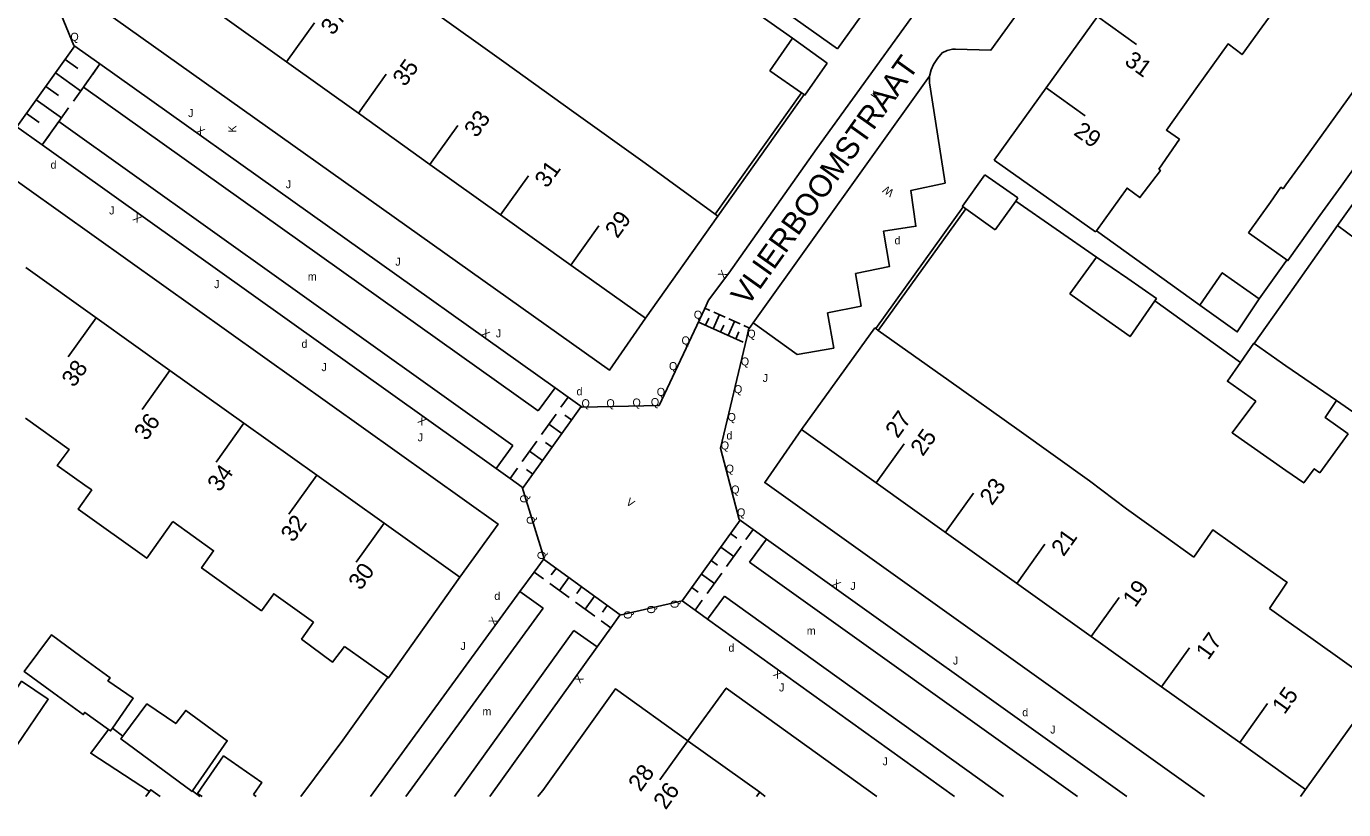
# Model space of a CAD drawing. Extents: x 134999 to 136502, y 457398 to 459002.
# Drawn here: x 135421.3 to 135503.6, y 457399.2 to 457448.2 of the extents above; entities that cross this region are included whole.
import ezdxf

# ---------------------------------------------------------------- set-up
doc = ezdxf.new("R2010")
doc.units = 0
for name, color, linetype in [('RI_DGTB_15', 7, 'Continuous'), ('RI_DGTB_29', 7, 'Continuous'), ('RI_DGTB_30', 7, 'Continuous'), ('RI_DGTB_31', 7, 'Continuous'), ('RI_DGTB_35', 7, 'Continuous'), ('RI_DGTB_36', 7, 'Continuous'), ('RI_DGTB_37', 7, 'Continuous'), ('RI_DGTB_4', 7, 'Continuous'), ('RI_DGTB_43', 7, 'Continuous'), ('RI_DGTB_5', 7, 'Continuous'), ('RI_DGTB_53', 7, 'Continuous'), ('RI_DGTB_54', 7, 'Continuous'), ('RI_DGTB_6', 7, 'Continuous')]:
    doc.layers.add(name, color=color, linetype=linetype)

msp = doc.modelspace()

# ---------------------------------------------------------------- linework, layer by layer
at = {"layer": 'RI_DGTB_15'}
for p, q in [((135437.555, 457445.942), (135439.3, 457448.383)), ((135488.229, 457448.789), (135490.666, 457447.039)), ((135442.047, 457442.731), (135443.792, 457445.172)), ((135485.025, 457444.32), (135487.462, 457442.57)), ((135446.521, 457439.532), (135448.266, 457441.973)), ((135450.925, 457436.384), (135452.67, 457438.825)), ((135455.324, 457433.239), (135457.069, 457435.68)), ((135425.664, 457429.938), (135423.921, 457427.497)), ((135430.273, 457426.646), (135428.53, 457424.205)), ((135434.897, 457423.344), (135433.154, 457420.903)), ((135474.411, 457419.608), (135476.153, 457422.051)), ((135439.448, 457420.094), (135437.705, 457417.653)), ((135478.739, 457416.532), (135480.481, 457418.975)), ((135443.65, 457417.093), (135441.907, 457414.652)), ((135483.209, 457413.344), (135484.951, 457415.787)), ((135487.846, 457410.007), (135489.588, 457412.45)), ((135492.245, 457406.864), (135493.987, 457409.307)), ((135497.127, 457403.375), (135498.869, 457405.818)), ((135462.631, 457403.486), (135460.879, 457401.052)), ((135467.134, 457400.278), (135466.929, 457400))]:
    msp.add_line(p, q, dxfattribs=at)
at = {"layer": 'RI_DGTB_31'}
for p, q in [((135424.325, 457446.935), (135420.711, 457441.875)), ((135423.722, 457446.091), (135424.509, 457445.53)), ((135425.898, 457445.811), (135425.446, 457445.178)), ((135423.12, 457445.248), (135424.693, 457444.124)), ((135422.518, 457444.405), (135423.304, 457443.843)), ((135421.915, 457443.561), (135423.489, 457442.438)), ((135421.313, 457442.718), (135422.1, 457442.156)), ((135423.94, 457443.07), (135423.037, 457441.805)), ((135422.736, 457441.384), (135422.284, 457440.751)), ((135463.664, 457430.561), (135464.018, 457430.402)), ((135464.212, 457429.257), (135464.607, 457430.138)), ((135464.253, 457430.297), (135464.961, 457429.979)), ((135463.269, 457429.68), (135466.098, 457428.411)), ((135463.74, 457429.468), (135463.938, 457429.909)), ((135464.683, 457429.045), (135464.881, 457429.486)), ((135465.155, 457428.834), (135465.55, 457429.715)), ((135465.196, 457429.874), (135465.904, 457429.556)), ((135466.139, 457429.451), (135466.493, 457429.292)), ((135465.626, 457428.622), (135465.824, 457429.063)), ((135452.311, 457419.262), (135455.966, 457424.395)), ((135453.493, 457422.646), (135454.397, 457423.916)), ((135455.363, 457423.548), (135454.955, 457423.838)), ((135454.76, 457422.701), (135453.945, 457423.281)), ((135452.287, 457420.952), (135453.191, 457422.222)), ((135454.157, 457421.854), (135453.749, 457422.144)), ((135453.554, 457421.007), (135452.739, 457421.587)), ((135451.533, 457419.893), (135451.985, 457420.528)), ((135452.951, 457420.16), (135452.544, 457420.45)), ((135465.903, 457417.282), (135462.275, 457412.228)), ((135465.299, 457416.44), (135465.705, 457416.148)), ((135464.694, 457415.598), (135465.506, 457415.014)), ((135465.96, 457415.646), (135465.053, 457414.383)), ((135458.403, 457411.355), (135453.612, 457414.841)), ((135464.089, 457414.755), (135464.495, 457414.464)), ((135454.398, 457414.269), (135454.104, 457413.864)), ((135455.199, 457413.686), (135454.611, 457412.877)), ((135463.484, 457413.913), (135464.297, 457413.33)), ((135464.75, 457413.961), (135463.843, 457412.698)), ((135455.212, 457412.44), (135454.01, 457413.314)), ((135456, 457413.103), (135455.706, 457412.699)), ((135462.879, 457413.071), (135463.286, 457412.779)), ((135456.814, 457411.275), (135455.612, 457412.149)), ((135456.801, 457412.52), (135456.213, 457411.712)), ((135457.602, 457411.937), (135457.308, 457411.533))]:
    msp.add_line(p, q, dxfattribs=at)
for points in [[(135424.861, 457444.359), (135424.242, 457443.492)], [(135425.145, 457444.757), (135424.861, 457444.359)], [(135454.699, 457424.34), (135455.15, 457424.974)], [(135466.714, 457416.696), (135466.262, 457416.067)], [(135453.61, 457413.606), (135453.023, 457414.033)], [(135463.541, 457412.277), (135463.085, 457411.643)], [(135457.82, 457410.542), (135457.214, 457410.983)]]:
    msp.add_lwpolyline(points, dxfattribs=at)
at = {"layer": 'RI_DGTB_4'}
for p, q in [((135433.115, 457449.117), (135437.555, 457445.942)), ((135485.025, 457444.32), (135488.229, 457448.789)), ((135437.555, 457445.942), (135442.047, 457442.731)), ((135442.047, 457442.731), (135446.521, 457439.532)), ((135446.521, 457439.532), (135450.925, 457436.384)), ((135450.925, 457436.384), (135455.324, 457433.239)), ((135459.986, 457429.906), (135464.513, 457436.297)), ((135421.273, 457433.073), (135425.72, 457429.897)), ((135455.324, 457433.239), (135459.986, 457429.906)), ((135425.72, 457429.897), (135430.273, 457426.646)), ((135474.317, 457429.306), (135469.741, 457422.945)), ((135430.273, 457426.646), (135434.897, 457423.344)), ((135434.897, 457423.344), (135439.448, 457420.094)), ((135469.741, 457422.945), (135474.411, 457419.608)), ((135439.448, 457420.094), (135443.65, 457417.093)), ((135474.411, 457419.608), (135478.802, 457416.47)), ((135443.65, 457417.093), (135448.391, 457413.708)), ((135478.802, 457416.47), (135483.18, 457413.342)), ((135483.18, 457413.342), (135487.846, 457410.007)), ((135487.846, 457410.007), (135492.245, 457406.864)), ((135443.891, 457407.453), (135441.185, 457409.389)), ((135492.245, 457406.864), (135497.127, 457403.375)), ((135505.842, 457406.869), (135501.241, 457400.435)), ((135462.666, 457403.458), (135462.63, 457403.484)), ((135467.134, 457400.278), (135462.666, 457403.458)), ((135497.127, 457403.375), (135500, 457401.322)), ((135500, 457401.322), (135501.241, 457400.435)), ((135467.476, 457400), (135467.134, 457400.278))]:
    msp.add_line(p, q, dxfattribs=at)
for points in [[(135471.987, 457446.759), (135475.354, 457451.47)], [(135465.542, 457451.338), (135471.987, 457446.759)], [(135481.788, 457439.804), (135485.025, 457444.32)], [(135488.119, 457435.306), (135481.788, 457439.804)], [(135448.391, 457413.708), (135443.937, 457407.42), (135443.891, 457407.453)], [(135462.63, 457403.484), (135458.11, 457406.733), (135453.564, 457400.374)], [(135453.564, 457400.374), (135453.553, 457400.358), (135453.271, 457400)]]:
    msp.add_lwpolyline(points, dxfattribs=at)
at = {"layer": 'RI_DGTB_5'}
for p, q in [((135451.135, 457445.939), (135446.56, 457449.221)), ((135455.512, 457442.798), (135459.97, 457439.599)), ((135493.367, 457441.101), (135492.071, 457439.225)), ((135459.97, 457439.599), (135464.337, 457436.422)), ((135464.337, 457436.422), (135464.513, 457436.297)), ((135488.119, 457435.306), (135488.169, 457435.376)), ((135474.317, 457429.306), (135474.375, 457429.265)), ((135474.375, 457429.265), (135474.538, 457429.149)), ((135478.942, 457426.012), (135474.538, 457429.149)), ((135483.338, 457422.88), (135478.942, 457426.012)), ((135487.735, 457419.748), (135483.338, 457422.88)), ((135490.039, 457417.985), (135487.735, 457419.748)), ((135492.406, 457416.299), (135490.039, 457417.985)), ((135492.406, 457416.299), (135494.264, 457414.975)), ((135497.893, 457414.929), (135500, 457413.455)), ((135500, 457413.274), (135498.979, 457411.765)), ((135501.718, 457409.812), (135500, 457411.037)), ((135505.71, 457406.962), (135501.718, 457409.812)), ((135428.99, 457400.307), (135428.771, 457400))]:
    msp.add_line(p, q, dxfattribs=at)
for points in [[(135500, 457451.96), (135499.054, 457450.673), (135499.902, 457450.04), (135498.524, 457448.136)], [(135494.494, 457444.406), (135496.395, 457447.068), (135497.27, 457446.403), (135498.524, 457448.136)], [(135451.135, 457445.939), (135455.512, 457442.798)], [(135494.494, 457444.406), (135492.541, 457441.672), (135493.367, 457441.101)], [(135488.169, 457435.376), (135490.085, 457438.051), (135490.881, 457437.451), (135492.168, 457439.155), (135492.071, 457439.225)], [(135425.099, 457419.373), (135423.232, 457420.694), (135423.972, 457421.708), (135421.244, 457423.66)], [(135425.099, 457419.373), (135425.387, 457419.169)], [(135430.456, 457417.188), (135428.821, 457414.903), (135424.531, 457417.972), (135425.387, 457419.169)], [(135434.298, 457412.829), (135432.249, 457414.295), (135432.994, 457415.372), (135430.456, 457417.188)], [(135497.893, 457414.929), (135495.435, 457416.671), (135494.264, 457414.975)], [(135434.298, 457412.829), (135435.988, 457411.62), (135436.762, 457412.676), (135439.241, 457410.903)], [(135500, 457413.455), (135500.083, 457413.397), (135500, 457413.274)], [(135500, 457411.037), (135498.979, 457411.765)], [(135441.185, 457409.389), (135440.432, 457408.41), (135438.499, 457409.843), (135439.241, 457410.903)], [(135429.662, 457400), (135429.074, 457400.425), (135428.99, 457400.307)]]:
    msp.add_lwpolyline(points, dxfattribs=at)
at = {"layer": 'RI_DGTB_53'}
msp.add_line((135500.93, 457400), (135501.241, 457400.435), dxfattribs=at)
at = {"layer": 'RI_DGTB_54'}
for p, q in [((135422.079, 457452.308), (135424.272, 457446.97)), ((135469.171, 457447.422), (135464.25, 457450.924)), ((135424.272, 457446.97), (135425.898, 457445.811)), ((135477.747, 457445.046), (135466.723, 457429.626)), ((135464.337, 457436.422), (135469.736, 457444.01)), ((135464.513, 457436.297), (135469.902, 457443.898)), ((135420.645, 457441.92), (135422.284, 457440.751)), ((135474.375, 457429.265), (135479.848, 457436.875)), ((135474.538, 457429.149), (135480.01, 457436.758)), ((135488.173, 457433.737), (135483.124, 457437.237)), ((135488.169, 457435.376), (135494.628, 457430.733)), ((135503.23, 457435.712), (135500, 457431.13)), ((135498.333, 457431.12), (135500, 457433.465)), ((135500, 457433.465), (135500.066, 457433.558)), ((135491.821, 457430.997), (135497.165, 457427.142)), ((135500, 457431.13), (135498.032, 457428.339)), ((135455.15, 457424.974), (135456.031, 457424.346)), ((135503.176, 457424.758), (135507.02, 457422.089)), ((135451.531, 457419.89), (135452.283, 457419.354)), ((135453.65, 457414.894), (135452.283, 457419.354)), ((135466.714, 457416.696), (135465.849, 457417.314)), ((135453.023, 457414.033), (135453.65, 457414.894)), ((135462.272, 457412.227), (135458.388, 457411.334)), ((135462.272, 457412.227), (135463.085, 457411.643)), ((135457.82, 457410.542), (135458.388, 457411.334)), ((135426.684, 457404.277), (135427.338, 457403.783)), ((135432.133, 457400), (135431.678, 457400.35))]:
    msp.add_line(p, q, dxfattribs=at)
for points in [[(135459.986, 457429.906), (135457.731, 457426.656), (135426.083, 457449.181), (135428.447, 457452.454)], [(135482.281, 457452.917), (135482.084, 457452.791), (135481.773, 457452.673), (135481.442, 457452.632), (135479.846, 457452.672), (135479.791, 457452.672), (135479.548, 457452.625), (135479.332, 457452.503), (135470.691, 457440.521), (135465.191, 457432.721), (135463.924, 457431.031)], [(135477.747, 457445.046), (135477.842, 457445.445), (135477.985, 457445.771), (135478.23, 457446.158), (135478.526, 457446.508), (135478.832, 457446.656), (135479.164, 457446.73), (135479.357, 457446.736), (135481.578, 457446.678), (135483.914, 457449.95)], [(135424.861, 457444.359), (135425.898, 457445.811)], [(135425.898, 457445.811), (135454.34, 457425.551)], [(135478.723, 457438.35), (135477.797, 457444.232), (135477.732, 457444.637), (135477.747, 457445.046)], [(135453.284, 457424.111), (135424.861, 457444.359)], [(135423.322, 457442.203), (135422.284, 457440.751)], [(135451.706, 457421.958), (135423.322, 457442.203)], [(135422.284, 457440.751), (135450.65, 457420.518)], [(135448.391, 457413.708), (135450.774, 457417.04), (135419.201, 457439.545), (135416.867, 457436.219)], [(135471.751, 457428.043), (135471.373, 457430.243), (135473.463, 457430.673), (135473.118, 457432.701), (135475.241, 457433.151), (135474.861, 457435.351), (135476.884, 457435.663), (135476.57, 457437.896), (135478.723, 457438.35)], [(135463.924, 457431.031), (135463.688, 457430.528)], [(135463.688, 457430.528), (135460.836, 457424.454), (135456.031, 457424.346)], [(135466.312, 457428.709), (135466.431, 457429.212), (135466.723, 457429.626)], [(135466.723, 457429.626), (135469.468, 457427.645), (135471.751, 457428.043)], [(135466.312, 457428.709), (135464.679, 457421.783), (135465.849, 457417.314)], [(135454.34, 457425.551), (135453.284, 457424.111)], [(135454.34, 457425.551), (135455.15, 457424.974)], [(135494.932, 457400), (135467.439, 457419.628), (135469.741, 457422.945)], [(135450.65, 457420.518), (135451.706, 457421.958)], [(135450.65, 457420.518), (135451.531, 457419.89)], [(135466.489, 457414.663), (135467.545, 457416.102)], [(135467.545, 457416.102), (135466.714, 457416.696)], [(135490.061, 457400), (135467.545, 457416.102)], [(135486.993, 457400), (135466.489, 457414.663)], [(135452.138, 457412.816), (135453.023, 457414.033)], [(135442.815, 457400), (135452.138, 457412.816)], [(135453.588, 457411.775), (135452.138, 457412.816)], [(135464.919, 457412.524), (135463.862, 457411.085)], [(135482.361, 457400), (135464.919, 457412.524)], [(135445.022, 457400), (135453.588, 457411.775)], [(135463.085, 457411.643), (135463.862, 457411.085)], [(135448.056, 457400), (135455.515, 457410.392)], [(135455.515, 457410.392), (135456.966, 457409.352)], [(135456.966, 457409.352), (135457.82, 457410.542)], [(135463.862, 457411.085), (135479.301, 457400)], [(135450.253, 457400), (135456.966, 457409.352)], [(135443.891, 457407.453), (135441.075, 457403.517), (135438.447, 457400)], [(135474.441, 457400), (135465.036, 457406.785), (135462.63, 457403.484)], [(135428.99, 457400.307), (135425.321, 457402.701), (135426.433, 457404.19)]]:
    msp.add_lwpolyline(points, dxfattribs=at)
at = {"layer": 'RI_DGTB_6'}
for p, q in [((135467.755, 457445.383), (135469.171, 457447.422)), ((135469.902, 457443.898), (135469.736, 457444.01)), ((135479.848, 457436.875), (135480.01, 457436.758)), ((135497.677, 457435.251), (135499.043, 457437.179)), ((135486.516, 457431.431), (135488.173, 457433.737)), ((135486.516, 457431.431), (135488.173, 457433.737)), ((135500, 457433.605), (135500.066, 457433.558)), ((135503.176, 457424.758), (135500, 457426.933)), ((135503.896, 457422.688), (135502.121, 457420.246))]:
    msp.add_line(p, q, dxfattribs=at)
for points in [[(135469.171, 457447.422), (135471.336, 457445.858)], [(135471.336, 457445.858), (135469.951, 457443.864), (135469.902, 457443.898)], [(135469.736, 457444.01), (135467.755, 457445.383)], [(135501.121, 457439.797), (135504.237, 457444.1), (135506.448, 457442.484)], [(135506.448, 457442.484), (135504.594, 457439.924), (135504.675, 457439.864), (135503.457, 457438.172)], [(135500, 457438.248), (135501.121, 457439.797)], [(135481.196, 457438.884), (135479.793, 457436.915), (135479.848, 457436.875)], [(135483.266, 457437.436), (135481.196, 457438.884)], [(135499.043, 457437.179), (135499.699, 457438.105), (135499.829, 457438.012)], [(135499.829, 457438.012), (135500, 457438.248)], [(135503.457, 457438.172), (135502.139, 457436.342)], [(135480.01, 457436.758), (135481.844, 457435.44)], [(135483.124, 457437.237), (135481.844, 457435.44)], [(135483.266, 457437.436), (135483.124, 457437.237)], [(135503.23, 457435.712), (135504.493, 457437.452)], [(135502.139, 457436.342), (135500.133, 457433.511), (135500.066, 457433.558)], [(135497.677, 457435.251), (135500, 457433.605)], [(135506.754, 457435.81), (135505.48, 457434.052), (135503.23, 457435.712)], [(135490.123, 457432.386), (135488.173, 457433.737)], [(135498.333, 457431.12), (135496.031, 457432.751), (135494.628, 457430.733)], [(135491.821, 457430.997), (135491.92, 457431.14), (135490.123, 457432.386)], [(135486.516, 457431.431), (135488.448, 457430.056)], [(135488.448, 457430.056), (135490.27, 457428.759), (135491.821, 457430.997)], [(135494.628, 457430.733), (135496.966, 457429.054), (135498.333, 457431.12)], [(135497.165, 457427.142), (135498.005, 457428.358), (135498.032, 457428.339)], [(135499.787, 457427.085), (135498.032, 457428.339)], [(135498.137, 457424.728), (135496.358, 457425.973), (135497.165, 457427.142)], [(135500, 457426.933), (135499.787, 457427.085)], [(135500, 457420.395), (135496.644, 457422.744), (135498.137, 457424.728)], [(135503.896, 457422.688), (135502.454, 457423.704), (135503.176, 457424.758)], [(135500, 457420.395), (135501.121, 457419.611), (135501.78, 457420.493), (135502.121, 457420.246)], [(135423.019, 457406.463), (135421.162, 457407.823), (135422.863, 457410.102), (135424.697, 457408.766)], [(135424.697, 457408.766), (135426.531, 457407.431), (135426.392, 457407.24), (135427.982, 457406.146), (135426.684, 457404.277)], [(135419.524, 457405.053), (135420.996, 457407.213), (135422.664, 457406.077), (135420.682, 457403.168), (135420.22, 457403.483)], [(135426.433, 457404.19), (135424.948, 457405.254), (135424.851, 457405.121), (135423.019, 457406.463)], [(135427.338, 457403.783), (135428.834, 457405.794), (135430.638, 457404.558), (135431.263, 457405.38), (135433.848, 457403.492), (135431.678, 457400.35)], [(135426.684, 457404.277), (135426.56, 457404.099), (135426.433, 457404.19)], [(135431.678, 457400.35), (135431.651, 457400.311), (135427.206, 457403.6), (135427.338, 457403.783)], [(135432.278, 457400), (135432, 457400.193), (135433.626, 457402.534), (135436.01, 457400.879), (135435.49, 457400.129)], [(135435.67, 457400), (135435.49, 457400.129)]]:
    msp.add_lwpolyline(points, dxfattribs=at)

# ---------------------------------------------------------------- texts
at = {"layer": 'RI_DGTB_29'}
for p in [(135422.812, 457439.261), (135475.552, 457434.531), (135438.492, 457428.061), (135455.682, 457425.091), (135465.045, 457422.327), (135450.54, 457412.292), (135465.172, 457409.053), (135483.534, 457405.018)]:
    msp.add_text('d', height=0.5, dxfattribs=at).set_placement(p)
at = {"layer": 'RI_DGTB_30'}
for s, height, rotation, p in [('K', 0.5, 54.47017, (135474.423, 457443.554)), ('X', 0.5, 324.49502, (135431.852, 457441.545)), ('K', 0.5, 90, (135434.411, 457441.519)), ('W', 0.5, 145.66812, (135475.559, 457437.876)), ('X', 0.499, 144.54404, (135428.554, 457436.227)), ('X', 0.499, 53.12999, (135464.891, 457432.322)), ('X', 0.499, 324.54404, (135449.678, 457428.867)), ('X', 0.499, 144.54404, (135446.349, 457423.571)), ('V', 0.499, 324.44244, (135458.727, 457418.309)), ('X', 0.499, 324.5094, (135471.597, 457413.214)), ('X', 0.499, 54.18324, (135450.552, 457410.638)), ('X', 0.499, 144.5094, (135468.574, 457407.733)), ('X', 0.499, 234.18532, (135455.75, 457407.676))]:
    msp.add_text(s, height=height, rotation=rotation, dxfattribs=at).set_placement(p)
at = {"layer": 'RI_DGTB_31'}
for s, p in [('Q', (135424.052, 457447.263)), ('J', (135431.409, 457442.49)), ('J', (135437.511, 457438.037)), ('J', (135426.476, 457436.401)), ('J', (135444.356, 457433.197)), ('J', (135433.035, 457431.793)), ('Q', (135463.009, 457429.884)), ('J', (135450.641, 457428.712)), ('Q', (135462.241, 457428.272)), ('Q', (135466.353, 457428.693)), ('J', (135439.742, 457426.601)), ('Q', (135461.457, 457426.667)), ('Q', (135465.945, 457426.955)), ('J', (135467.309, 457425.924)), ('Q', (135460.695, 457425.054)), ('Q', (135465.519, 457425.22)), ('Q', (135455.99, 457424.344)), ('Q', (135457.547, 457424.345)), ('Q', (135459.176, 457424.389)), ('Q', (135460.324, 457424.418)), ('Q', (135465.117, 457423.482)), ('J', (135445.752, 457422.211)), ('Q', (135464.694, 457421.701)), ('Q', (135465, 457420.256)), ('Q', (135465.344, 457418.948)), ('Q', (135465.708, 457417.52)), ('J', (135472.79, 457412.919)), ('J', (135448.426, 457409.167)), ('J', (135479.201, 457408.253)), ('J', (135468.333, 457406.57)), ('J', (135485.281, 457403.938)), ('J', (135474.805, 457401.95))]:
    msp.add_text(s, height=0.5, dxfattribs=at).set_placement(p)
for p in [(135452.658, 457418.358), (135453.069, 457417.02), (135453.743, 457414.821), (135462.058, 457411.768), (135459.134, 457411.096), (135460.596, 457411.432)]:
    msp.add_text('Q', height=0.5, rotation=90, dxfattribs=at).set_placement(p)
at = {"layer": 'RI_DGTB_35'}
for s, rotation, p in [('29', 324.3057, (135486.687, 457441.422)), ('29', 54.4369, (135458.234, 457434.85)), ('27', 54.5131, (135475.75, 457422.347)), ('30', 54.4716, (135442.197, 457412.841)), ('15', 54.5037, (135499.918, 457405.08)), ('28', 54.2576, (135459.68, 457400.242))]:
    msp.add_text(s, height=1.054, rotation=rotation, dxfattribs=at).set_placement(p)
at = {"layer": 'RI_DGTB_36'}
for s, rotation, p in [('37', 54.4369, (135440.465, 457447.553)), ('31', 324.3057, (135489.86, 457445.839)), ('35', 54.4369, (135444.958, 457444.344)), ('33', 54.4369, (135449.432, 457441.145)), ('31', 54.4369, (135453.836, 457437.997)), ('38', 54.4716, (135424.276, 457425.532)), ('36', 54.4716, (135428.802, 457422.197)), ('25', 54.5037, (135477.319, 457421.224)), ('34', 54.4716, (135433.379, 457418.992)), ('23', 54.5037, (135481.647, 457418.148)), ('32', 54.4716, (135437.969, 457415.842)), ('21', 54.5037, (135486.116, 457414.959)), ('19', 54.5037, (135490.586, 457411.771)), ('17', 54.5037, (135495.152, 457408.48)), ('26', 54.2576, (135461.251, 457399.119))]:
    msp.add_text(s, height=1.054, rotation=rotation, dxfattribs=at).set_placement(p)
at = {"layer": 'RI_DGTB_37'}
msp.add_text('VLIERBOOMSTRAAT', height=1.4, rotation=54.52108, dxfattribs=at).set_placement((135466.37, 457430.592))
at = {"layer": 'RI_DGTB_43'}
for p in [(135438.887, 457432.269), (135470.068, 457410.118), (135449.8, 457405.074)]:
    msp.add_text('m', height=0.5, dxfattribs=at).set_placement(p)

doc.saveas('drawing.dxf')
